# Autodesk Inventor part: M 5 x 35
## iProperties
IsCustomPart: 0
Company: 한국ATC센터
Created: 2014-12
Part Number: M 5 x 35
Material: 강, 연강
Description: 6각머리 태핑 나사
Document SubType Name: Modeling
Standard: KS B 1003
Designer: KYOUNG IL JANG
Standards Organization: KS
Language: ko-KR
Size Designation: M 5 x 35
Categories: <MemberInstance><Categories><Category DisplayName="조임쇠" InternalName="e4da775c-781d-43d5-af7c-5136215cf5a6" Mnemonic="FSTN"><Category DisplayName="볼트" InternalN
Density: 7.86 g/cm^3
Mass: 7.27786 g
Surface Area: 8.23857 cm^2
Volume: 0.925936 cm^3
Author: KYOUNG IL JANG
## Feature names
1. Fillet2
